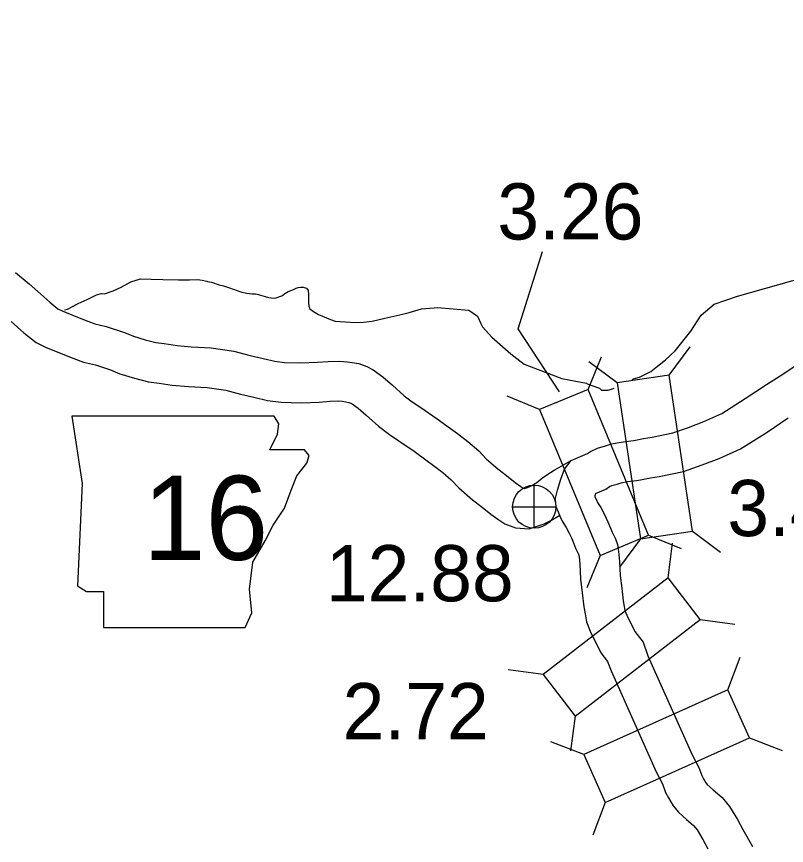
# Model space of a CAD drawing. Extents: x 0 to 3171, y 0 to 2059.
# Drawn here: x 160.1 to 276, y 1415.2 to 1539.9 of the extents above; entities that cross this region are included whole.
import ezdxf

# ---------------------------------------------------------------- set-up
doc = ezdxf.new("R2010")
doc.units = 0
for name, color, linetype in [('Default', 7, 'Continuous'), ('Level 10', 7, 'Continuous'), ('Level 20', 7, 'Continuous'), ('Level 21', 7, 'Continuous'), ('Level 25', 7, 'Continuous'), ('Level 26', 7, 'Continuous'), ('Level 58', 7, 'Continuous'), ('Level 8', 7, 'Continuous')]:
    doc.layers.add(name, color=color, linetype=linetype)

msp = doc.modelspace()

# ---------------------------------------------------------------- linework, layer by layer
at = {"layer": 'Default'}
msp.add_circle((410.95, 1647.45), 386.47, dxfattribs=at)
msp.add_circle((410.95, 1647.45), 386.47, dxfattribs=at)
at = {"layer": 'Level 10'}
for points in [[(159.95, 1501.38), (162, 1499.69), (163.31, 1498.5), (165.11, 1496.91), (166.31, 1495.94), (166.98, 1495.6), (169.05, 1494.75), (170.85, 1494.04), (171.92, 1493.66), (173.63, 1493.26), (176.35, 1492.35), (177.71, 1491.8), (179.5, 1491.24), (181.08, 1490.84), (182.36, 1490.69), (184.28, 1490.41), (186.42, 1490.2), (189.41, 1490.07), (192.81, 1489.55), (195.29, 1488.91), (197.23, 1488.45), (198.97, 1488.04), (200.45, 1487.86), (202.91, 1487.78), (205.35, 1487.88), (207, 1488), (208.79, 1488.06), (209.9, 1487.95), (210.64, 1487.84), (211.65, 1487.67), (212.83, 1487.25), (213.78, 1486.75), (215.26, 1485.7), (216.73, 1484.42), (218.46, 1482.85), (219.69, 1481.9), (220.98, 1481.08), (223.43, 1479.38), (225.45, 1477.91), (226.48, 1477.16), (228.06, 1475.93), (229.7, 1474.55), (230.87, 1473.28), (232.54, 1471.83), (233.88, 1470.83), (235.19, 1469.79), (236.01, 1469.18), (236.33, 1468.96), (236.51, 1468.9), (236.55, 1468.9), (236.87, 1469), (237.28, 1469.14), (237.67, 1469.33), (238.43, 1469.79), (239.34, 1470.56), (240.49, 1471.3), (241.02, 1471.63), (243.58, 1473.12)], [(159.95, 1501.38), (162, 1499.69), (163.31, 1498.5), (165.11, 1496.91), (166.31, 1495.94), (166.98, 1495.6), (169.05, 1494.75), (170.85, 1494.04), (171.92, 1493.66), (173.63, 1493.26), (176.35, 1492.35), (177.71, 1491.8), (179.5, 1491.24), (181.08, 1490.84), (182.36, 1490.69), (184.28, 1490.41), (186.42, 1490.2), (189.41, 1490.07), (192.81, 1489.55), (195.29, 1488.91), (197.23, 1488.45), (198.97, 1488.04), (200.45, 1487.86), (202.91, 1487.78), (205.35, 1487.88), (207, 1488), (208.79, 1488.06), (209.9, 1487.95), (210.64, 1487.84), (211.65, 1487.67), (212.83, 1487.25), (213.78, 1486.75), (215.26, 1485.7), (216.73, 1484.42), (218.46, 1482.85), (219.69, 1481.9), (220.98, 1481.08), (223.43, 1479.38), (225.45, 1477.91), (226.48, 1477.16), (228.06, 1475.93), (229.7, 1474.55), (230.87, 1473.28), (232.54, 1471.83), (233.88, 1470.83), (235.19, 1469.79), (236.01, 1469.18), (236.33, 1468.96), (236.51, 1468.9), (236.55, 1468.9), (236.87, 1469), (237.28, 1469.14), (237.67, 1469.33), (238.43, 1469.79), (239.34, 1470.56), (240.49, 1471.3), (241.02, 1471.63), (243.58, 1473.12)], [(159.32, 1494.03), (161.23, 1492.33), (163.05, 1490.85), (164.5, 1490.14), (166.81, 1489.18), (168.73, 1488.43), (170.21, 1487.89), (172.01, 1487.48), (174.27, 1486.73), (175.67, 1486.15), (177.87, 1485.46), (180, 1484.92), (181.58, 1484.74), (183.54, 1484.45), (185.99, 1484.21), (188.83, 1484.09), (191.61, 1483.66), (193.85, 1483.09), (195.85, 1482.61), (197.9, 1482.13), (199.97, 1481.87), (202.94, 1481.77), (205.69, 1481.89), (207.32, 1482.01), (208.6, 1482.05), (209.13, 1482), (209.67, 1481.91), (210.14, 1481.84), (210.43, 1481.73), (210.64, 1481.62), (211.55, 1480.98), (212.74, 1479.94), (214.6, 1478.25), (216.24, 1476.99), (217.66, 1476.08), (219.95, 1474.49), (221.92, 1473.06), (222.88, 1472.36), (224.28, 1471.27), (225.55, 1470.19), (226.69, 1468.97), (228.77, 1467.16), (230.22, 1466.08), (231.53, 1465.03), (232.55, 1464.27), (233.62, 1463.56), (235.24, 1462.98), (237.28, 1462.82), (238.76, 1463.31), (239.54, 1463.57), (240.55, 1464.05), (241.9, 1464.88)], [(159.32, 1494.03), (161.23, 1492.33), (163.05, 1490.85), (164.5, 1490.14), (166.81, 1489.18), (168.73, 1488.43), (170.21, 1487.89), (172.01, 1487.48), (174.27, 1486.73), (175.67, 1486.15), (177.87, 1485.46), (180, 1484.92), (181.58, 1484.74), (183.54, 1484.45), (185.99, 1484.21), (188.83, 1484.09), (191.61, 1483.66), (193.85, 1483.09), (195.85, 1482.61), (197.9, 1482.13), (199.97, 1481.87), (202.94, 1481.77), (205.69, 1481.89), (207.32, 1482.01), (208.6, 1482.05), (209.13, 1482), (209.67, 1481.91), (210.14, 1481.84), (210.43, 1481.73), (210.64, 1481.62), (211.55, 1480.98), (212.74, 1479.94), (214.6, 1478.25), (216.24, 1476.99), (217.66, 1476.08), (219.95, 1474.49), (221.92, 1473.06), (222.88, 1472.36), (224.28, 1471.27), (225.55, 1470.19), (226.69, 1468.97), (228.77, 1467.16), (230.22, 1466.08), (231.53, 1465.03), (232.55, 1464.27), (233.62, 1463.56), (235.24, 1462.98), (237.28, 1462.82), (238.76, 1463.31), (239.54, 1463.57), (240.55, 1464.05), (241.9, 1464.88)], [(243.58, 1473.12), (246.06, 1474.15), (246.51, 1474.43), (247.56, 1474.94), (248.76, 1475.29), (249.66, 1475.58), (251.13, 1475.84), (252.56, 1476.05), (253.01, 1476.11), (254.48, 1476.41), (255.8, 1476.6), (258.92, 1477.24), (261.25, 1478.05), (263.55, 1478.95), (266.27, 1480.17), (269.81, 1482.41), (272.99, 1484.54), (275.61, 1486.19), (278.67, 1488.24)], [(243.58, 1473.12), (246.06, 1474.15), (246.51, 1474.43), (247.56, 1474.94), (248.76, 1475.29), (249.66, 1475.58), (251.13, 1475.84), (252.56, 1476.05), (253.01, 1476.11), (254.48, 1476.41), (255.8, 1476.6), (258.92, 1477.24), (261.25, 1478.05), (263.55, 1478.95), (266.27, 1480.17), (269.81, 1482.41), (272.99, 1484.54), (275.61, 1486.19), (278.67, 1488.24)], [(247.26, 1468.15), (248.8, 1468.79), (249.39, 1469.16), (249.74, 1469.32), (250.54, 1469.56), (251.11, 1469.75), (252.08, 1469.92), (253.41, 1470.11), (254.03, 1470.2), (255.52, 1470.5), (256.84, 1470.69), (260.51, 1471.44), (263.33, 1472.42), (265.87, 1473.42), (269.11, 1474.87), (273.08, 1477.38), (276.26, 1479.51)], [(247.26, 1468.15), (248.8, 1468.79), (249.39, 1469.16), (249.74, 1469.32), (250.54, 1469.56), (251.11, 1469.75), (252.08, 1469.92), (253.41, 1470.11), (254.03, 1470.2), (255.52, 1470.5), (256.84, 1470.69), (260.51, 1471.44), (263.33, 1472.42), (265.87, 1473.42), (269.11, 1474.87), (273.08, 1477.38), (276.26, 1479.51)], [(241.18, 1467.24), (241.55, 1468.61), (242.02, 1470.27), (242.61, 1471.8), (243.58, 1473.12)], [(241.18, 1467.24), (241.55, 1468.61), (242.02, 1470.27), (242.61, 1471.8), (243.58, 1473.12)], [(247.26, 1468.15), (247.16, 1467.77), (247.17, 1467.65), (247.4, 1467.19), (247.57, 1466.8), (248.06, 1466), (248.61, 1464.98), (249.12, 1463.89), (249.53, 1462.93), (249.76, 1462.32), (250.27, 1461.31), (250.55, 1460.48), (250.73, 1459.42), (250.86, 1457.92), (250.98, 1455.77), (251.2, 1453.88), (251.42, 1451.99), (251.58, 1451.12), (251.7, 1450.52), (251.97, 1449.84), (253.19, 1447.35), (254.41, 1445.77), (255.16, 1443.69), (261.81, 1428.83), (262.81, 1426.88), (263.26, 1425.7), (263.49, 1425.3), (263.87, 1424.61), (264.08, 1424.37), (264.97, 1423.56), (266.31, 1422.37), (267.44, 1421.04), (268.63, 1419.07), (269.43, 1417.58), (270.89, 1415)], [(247.26, 1468.15), (247.16, 1467.77), (247.17, 1467.65), (247.4, 1467.19), (247.57, 1466.8), (248.06, 1466), (248.61, 1464.98), (249.12, 1463.89), (249.53, 1462.93), (249.76, 1462.32), (250.27, 1461.31), (250.55, 1460.48), (250.73, 1459.42), (250.86, 1457.92), (250.98, 1455.77), (251.2, 1453.88), (251.42, 1451.99), (251.58, 1451.12), (251.7, 1450.52), (251.97, 1449.84), (253.19, 1447.35), (254.41, 1445.77), (255.16, 1443.69), (261.81, 1428.83), (262.81, 1426.88), (263.26, 1425.7), (263.49, 1425.3), (263.87, 1424.61), (264.08, 1424.37), (264.97, 1423.56), (266.31, 1422.37), (267.44, 1421.04), (268.63, 1419.07), (269.43, 1417.58), (270.89, 1415)], [(241.18, 1467.24), (241.31, 1466.17), (241.62, 1465.35), (241.96, 1464.64), (242.26, 1463.98), (242.85, 1463.02), (243.25, 1462.27), (243.65, 1461.44), (243.95, 1460.72), (244.25, 1459.92), (244.72, 1458.98), (244.78, 1458.66), (244.88, 1457.51), (244.99, 1455.26), (245.24, 1453.18), (245.48, 1451.1), (245.68, 1450.01), (245.92, 1448.81), (246.48, 1447.4), (248.07, 1444.16), (249.09, 1442.85), (249.6, 1441.44), (256.4, 1426.23), (257.32, 1424.44), (257.81, 1423.15), (258.26, 1422.34), (258.95, 1421.14), (259.77, 1420.18), (260.96, 1419.1), (262.01, 1418.17), (262.55, 1417.52), (263.42, 1416.09), (264.17, 1414.69)], [(241.18, 1467.24), (241.31, 1466.17), (241.62, 1465.35), (241.96, 1464.64), (242.26, 1463.98), (242.85, 1463.02), (243.25, 1462.27), (243.65, 1461.44), (243.95, 1460.72), (244.25, 1459.92), (244.72, 1458.98), (244.78, 1458.66), (244.88, 1457.51), (244.99, 1455.26), (245.24, 1453.18), (245.48, 1451.1), (245.68, 1450.01), (245.92, 1448.81), (246.48, 1447.4), (248.07, 1444.16), (249.09, 1442.85), (249.6, 1441.44), (256.4, 1426.23), (257.32, 1424.44), (257.81, 1423.15), (258.26, 1422.34), (258.95, 1421.14), (259.77, 1420.18), (260.96, 1419.1), (262.01, 1418.17), (262.55, 1417.52), (263.42, 1416.09), (264.17, 1414.69)]]:
    msp.add_lwpolyline(points, dxfattribs=at)
at = {"layer": 'Level 20'}
for p, q in [((258.35, 1485.96), (261.5, 1490.21)), ((258.35, 1485.96), (261.5, 1490.21)), ((246.14, 1483.8), (248.15, 1488.68)), ((246.14, 1483.8), (248.15, 1488.68)), ((250.52, 1484.8), (246.28, 1487.94)), ((250.52, 1484.8), (246.28, 1487.94)), ((238.83, 1480.76), (233.95, 1482.77)), ((238.83, 1480.76), (233.95, 1482.77)), ((255.26, 1461.86), (260.14, 1459.85)), ((255.26, 1461.86), (260.14, 1459.85)), ((261.86, 1462.46), (266.1, 1459.32)), ((261.86, 1462.46), (266.1, 1459.32)), ((254.02, 1461.3), (250.88, 1457.05)), ((254.02, 1461.3), (250.88, 1457.05)), ((258.18, 1455.43), (258.85, 1460.66)), ((258.18, 1455.43), (258.85, 1460.66)), ((247.95, 1458.82), (245.94, 1453.94)), ((247.95, 1458.82), (245.94, 1453.94)), ((263.01, 1449.16), (268.25, 1448.48)), ((263.01, 1449.16), (268.25, 1448.48)), ((267.18, 1438.58), (269.06, 1443.51)), ((267.18, 1438.58), (269.06, 1443.51)), ((239.36, 1440.92), (234.12, 1441.6)), ((239.36, 1440.92), (234.12, 1441.6)), ((244.2, 1434.65), (243.52, 1429.41)), ((244.2, 1434.65), (243.52, 1429.41)), ((245.49, 1428.87), (240.56, 1430.76)), ((245.49, 1428.87), (240.56, 1430.76)), ((270.42, 1431.35), (275.35, 1429.46)), ((270.42, 1431.35), (275.35, 1429.46)), ((248.73, 1421.64), (246.84, 1416.71)), ((248.73, 1421.64), (246.84, 1416.71))]:
    msp.add_line(p, q, dxfattribs=at)
for points in [[(261.86, 1462.46), (258.35, 1485.96), (250.52, 1484.8), (254.02, 1461.3)], [(261.86, 1462.46), (258.35, 1485.96), (250.52, 1484.8), (254.02, 1461.3)], [(255.26, 1461.86), (246.14, 1483.8), (238.83, 1480.76), (247.95, 1458.82)], [(255.26, 1461.86), (246.14, 1483.8), (238.83, 1480.76), (247.95, 1458.82)], [(258.18, 1455.43), (239.36, 1440.92), (244.2, 1434.65), (263.01, 1449.16)], [(258.18, 1455.43), (239.36, 1440.92), (244.2, 1434.65), (263.01, 1449.16)], [(267.18, 1438.58), (245.49, 1428.87), (248.73, 1421.64), (270.42, 1431.35)], [(267.18, 1438.58), (245.49, 1428.87), (248.73, 1421.64), (270.42, 1431.35)]]:
    msp.add_lwpolyline(points, close=True, dxfattribs=at)
at = {"layer": 'Level 21'}
msp.add_lwpolyline([(168.46, 1479.78), (169.98, 1469.62), (169.31, 1454.23), (170.66, 1453.38), (173.2, 1453.38), (173.2, 1447.97), (194.52, 1447.97), (195.53, 1450.17), (195.19, 1453.72), (195.7, 1457.78), (197.56, 1461), (198.74, 1463.37), (200.44, 1465.9), (201.45, 1468.61), (202.3, 1470.81), (203.82, 1472.67), (204.16, 1473.85), (203.48, 1474.7), (198.24, 1474.7), (199.42, 1477.07), (199.59, 1478.59), (198.89, 1479.76)], close=True, dxfattribs=at)
msp.add_lwpolyline([(168.46, 1479.78), (169.98, 1469.62), (169.31, 1454.23), (170.66, 1453.38), (173.2, 1453.38), (173.2, 1447.97), (194.52, 1447.97), (195.53, 1450.17), (195.19, 1453.72), (195.7, 1457.78), (197.56, 1461), (198.74, 1463.37), (200.44, 1465.9), (201.45, 1468.61), (202.3, 1470.81), (203.82, 1472.67), (204.16, 1473.85), (203.48, 1474.7), (198.24, 1474.7), (199.42, 1477.07), (199.59, 1478.59), (198.89, 1479.76)], close=True, dxfattribs=at)
at = {"layer": 'Level 26'}
for p, q in [((238.04, 1462.89), (238.04, 1469.39)), ((238.04, 1462.89), (238.04, 1469.39)), ((234.79, 1466.14), (241.29, 1466.14)), ((234.79, 1466.14), (241.29, 1466.14))]:
    msp.add_line(p, q, dxfattribs=at)
msp.add_circle((238.04, 1466.14), 3.25, dxfattribs=at)
msp.add_circle((238.04, 1466.14), 3.25, dxfattribs=at)
at = {"layer": 'Level 58'}
msp.add_lwpolyline([(241.83, 1483.42), (235.63, 1492.89), (239.28, 1504.56)], dxfattribs=at)
msp.add_lwpolyline([(241.83, 1483.42), (235.63, 1492.89), (239.28, 1504.56)], dxfattribs=at)
at = {"layer": 'Level 8'}
for points in [[(167.34, 1495.75), (167.8, 1495.85), (169.4, 1496.72), (170.76, 1497.34), (172.16, 1498.04), (172.92, 1498.2), (173.38, 1498.15), (174.66, 1498.63), (175.86, 1499.19), (177.3, 1499.97), (178.75, 1500.44), (180.39, 1500.38), (182.15, 1500.31), (184.5, 1500.28), (186.14, 1500.3), (187.36, 1500.32), (188.08, 1500.21), (188.78, 1500.07), (188.87, 1500.05), (189.47, 1499.95), (190.61, 1499.55), (191.25, 1499.36), (192.31, 1499.02), (192.59, 1498.94)], [(167.34, 1495.75), (167.8, 1495.85), (169.4, 1496.72), (170.76, 1497.34), (172.16, 1498.04), (172.92, 1498.2), (173.38, 1498.15), (174.66, 1498.63), (175.86, 1499.19), (177.3, 1499.97), (178.75, 1500.44), (180.39, 1500.38), (182.15, 1500.31), (184.5, 1500.28), (186.14, 1500.3), (187.36, 1500.32), (188.08, 1500.21), (188.78, 1500.07), (188.87, 1500.05), (189.47, 1499.95), (190.61, 1499.55), (191.25, 1499.36), (192.31, 1499.02), (192.59, 1498.94)], [(274.87, 1499.59), (275.39, 1499.72), (276.77, 1500.12), (277.79, 1500.38), (278.43, 1500.43), (279.33, 1500.45), (279.77, 1500.45), (280.33, 1500.21), (281, 1499.7)], [(274.87, 1499.59), (275.39, 1499.72), (276.77, 1500.12), (277.79, 1500.38), (278.43, 1500.43), (279.33, 1500.45), (279.77, 1500.45), (280.33, 1500.21), (281, 1499.7)], [(192.59, 1498.94), (192.92, 1498.82), (193.44, 1498.6), (194.04, 1498.42), (194.76, 1498.27), (195.6, 1498.19), (196.06, 1498.17), (196.56, 1498.07), (196.85, 1497.95), (197.55, 1497.76), (198.03, 1497.62), (198.43, 1497.56), (198.81, 1497.52), (199.17, 1497.56), (199.73, 1497.76), (200.15, 1497.94), (200.51, 1498.24), (200.99, 1498.5), (201.53, 1498.71), (201.79, 1498.83), (202.23, 1499.05), (202.53, 1499.13), (202.89, 1499.17), (203.27, 1499.17), (203.41, 1499.15), (203.74, 1499.01), (204, 1498.67), (204.06, 1498.11), (204.08, 1497.59), (204.06, 1496.86), (204.1, 1496.3), (204.24, 1495.9), (204.79, 1495.54), (205.55, 1495.08), (207.35, 1494.29), (208.06, 1494.07), (209.58, 1493.97), (211.14, 1493.88), (212.35, 1493.92), (213.63, 1494.07), (215.57, 1494.53), (217.79, 1495), (219.19, 1495.38), (221.06, 1495.91), (222.98, 1496.09), (223.48, 1496.13), (228.17, 1495.71), (229.52, 1494.83), (230, 1493.73), (230.26, 1493.19), (231.67, 1491.65)], [(192.59, 1498.94), (192.92, 1498.82), (193.44, 1498.6), (194.04, 1498.42), (194.76, 1498.27), (195.6, 1498.19), (196.06, 1498.17), (196.56, 1498.07), (196.85, 1497.95), (197.55, 1497.76), (198.03, 1497.62), (198.43, 1497.56), (198.81, 1497.52), (199.17, 1497.56), (199.73, 1497.76), (200.15, 1497.94), (200.51, 1498.24), (200.99, 1498.5), (201.53, 1498.71), (201.79, 1498.83), (202.23, 1499.05), (202.53, 1499.13), (202.89, 1499.17), (203.27, 1499.17), (203.41, 1499.15), (203.74, 1499.01), (204, 1498.67), (204.06, 1498.11), (204.08, 1497.59), (204.06, 1496.86), (204.1, 1496.3), (204.24, 1495.9), (204.79, 1495.54), (205.55, 1495.08), (207.35, 1494.29), (208.06, 1494.07), (209.58, 1493.97), (211.14, 1493.88), (212.35, 1493.92), (213.63, 1494.07), (215.57, 1494.53), (217.79, 1495), (219.19, 1495.38), (221.06, 1495.91), (222.98, 1496.09), (223.48, 1496.13), (228.17, 1495.71), (229.52, 1494.83), (230, 1493.73), (230.26, 1493.19), (231.67, 1491.65)], [(252.76, 1485.28), (252.96, 1485.37), (253.88, 1485.61), (255.6, 1486.5), (256.32, 1487.1), (257.8, 1488.24), (259.25, 1489.61), (261.59, 1492.55), (263.14, 1494.96), (265.11, 1496.63), (268.64, 1497.83), (274.87, 1499.59)], [(252.76, 1485.28), (252.96, 1485.37), (253.88, 1485.61), (255.6, 1486.5), (256.32, 1487.1), (257.8, 1488.24), (259.25, 1489.61), (261.59, 1492.55), (263.14, 1494.96), (265.11, 1496.63), (268.64, 1497.83), (274.87, 1499.59)], [(231.67, 1491.65), (234.52, 1489.15), (236.53, 1487.6), (238.63, 1486.78), (242.21, 1485.45), (244.32, 1485.02), (245.91, 1484.73), (246, 1484.64), (247.86, 1483.99), (248.18, 1483.69), (249.19, 1483.69), (250.08, 1483.97)], [(231.67, 1491.65), (234.52, 1489.15), (236.53, 1487.6), (238.63, 1486.78), (242.21, 1485.45), (244.32, 1485.02), (245.91, 1484.73), (246, 1484.64), (247.86, 1483.99), (248.18, 1483.69), (249.19, 1483.69), (250.08, 1483.97)]]:
    msp.add_lwpolyline(points, dxfattribs=at)

# ---------------------------------------------------------------- texts
at = {"layer": 'Level 21'}
msp.add_text('16', height=12.672, dxfattribs=at).set_placement((179.14, 1458.14))
msp.add_text('16', height=12.672, dxfattribs=at).set_placement((179.14, 1458.14))
at = {"layer": 'Level 25'}
msp.add_text('12.88', height=8.448, dxfattribs=at).set_placement((206.68, 1451.91))
msp.add_text('12.88', height=8.448, dxfattribs=at).set_placement((206.68, 1451.91))
at = {"layer": 'Level 58'}
for s, p in [('3.26', (232.49, 1506.35)), ('3.26', (232.49, 1506.35)), ('3.42', (267.1, 1461.72)), ('3.42', (267.1, 1461.72)), ('2.72', (209.2, 1431.16)), ('2.72', (209.2, 1431.16))]:
    msp.add_text(s, height=8.448, dxfattribs=at).set_placement(p)

doc.saveas('drawing.dxf')
